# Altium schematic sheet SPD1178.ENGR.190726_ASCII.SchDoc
size A1; Revision: V01; SheetNumber: 1; SheetTotal: 1
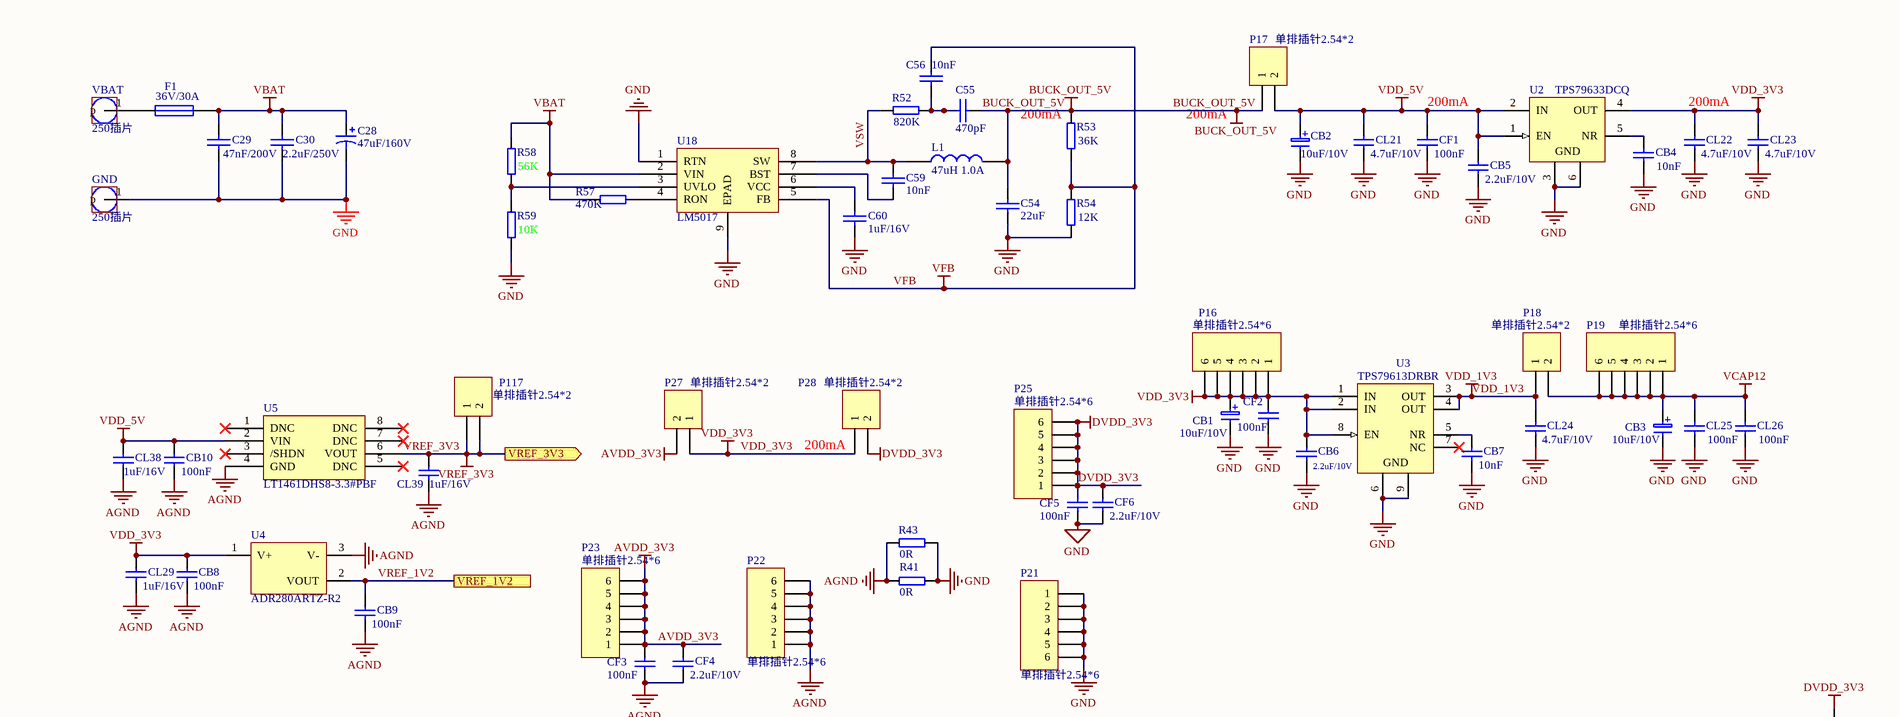
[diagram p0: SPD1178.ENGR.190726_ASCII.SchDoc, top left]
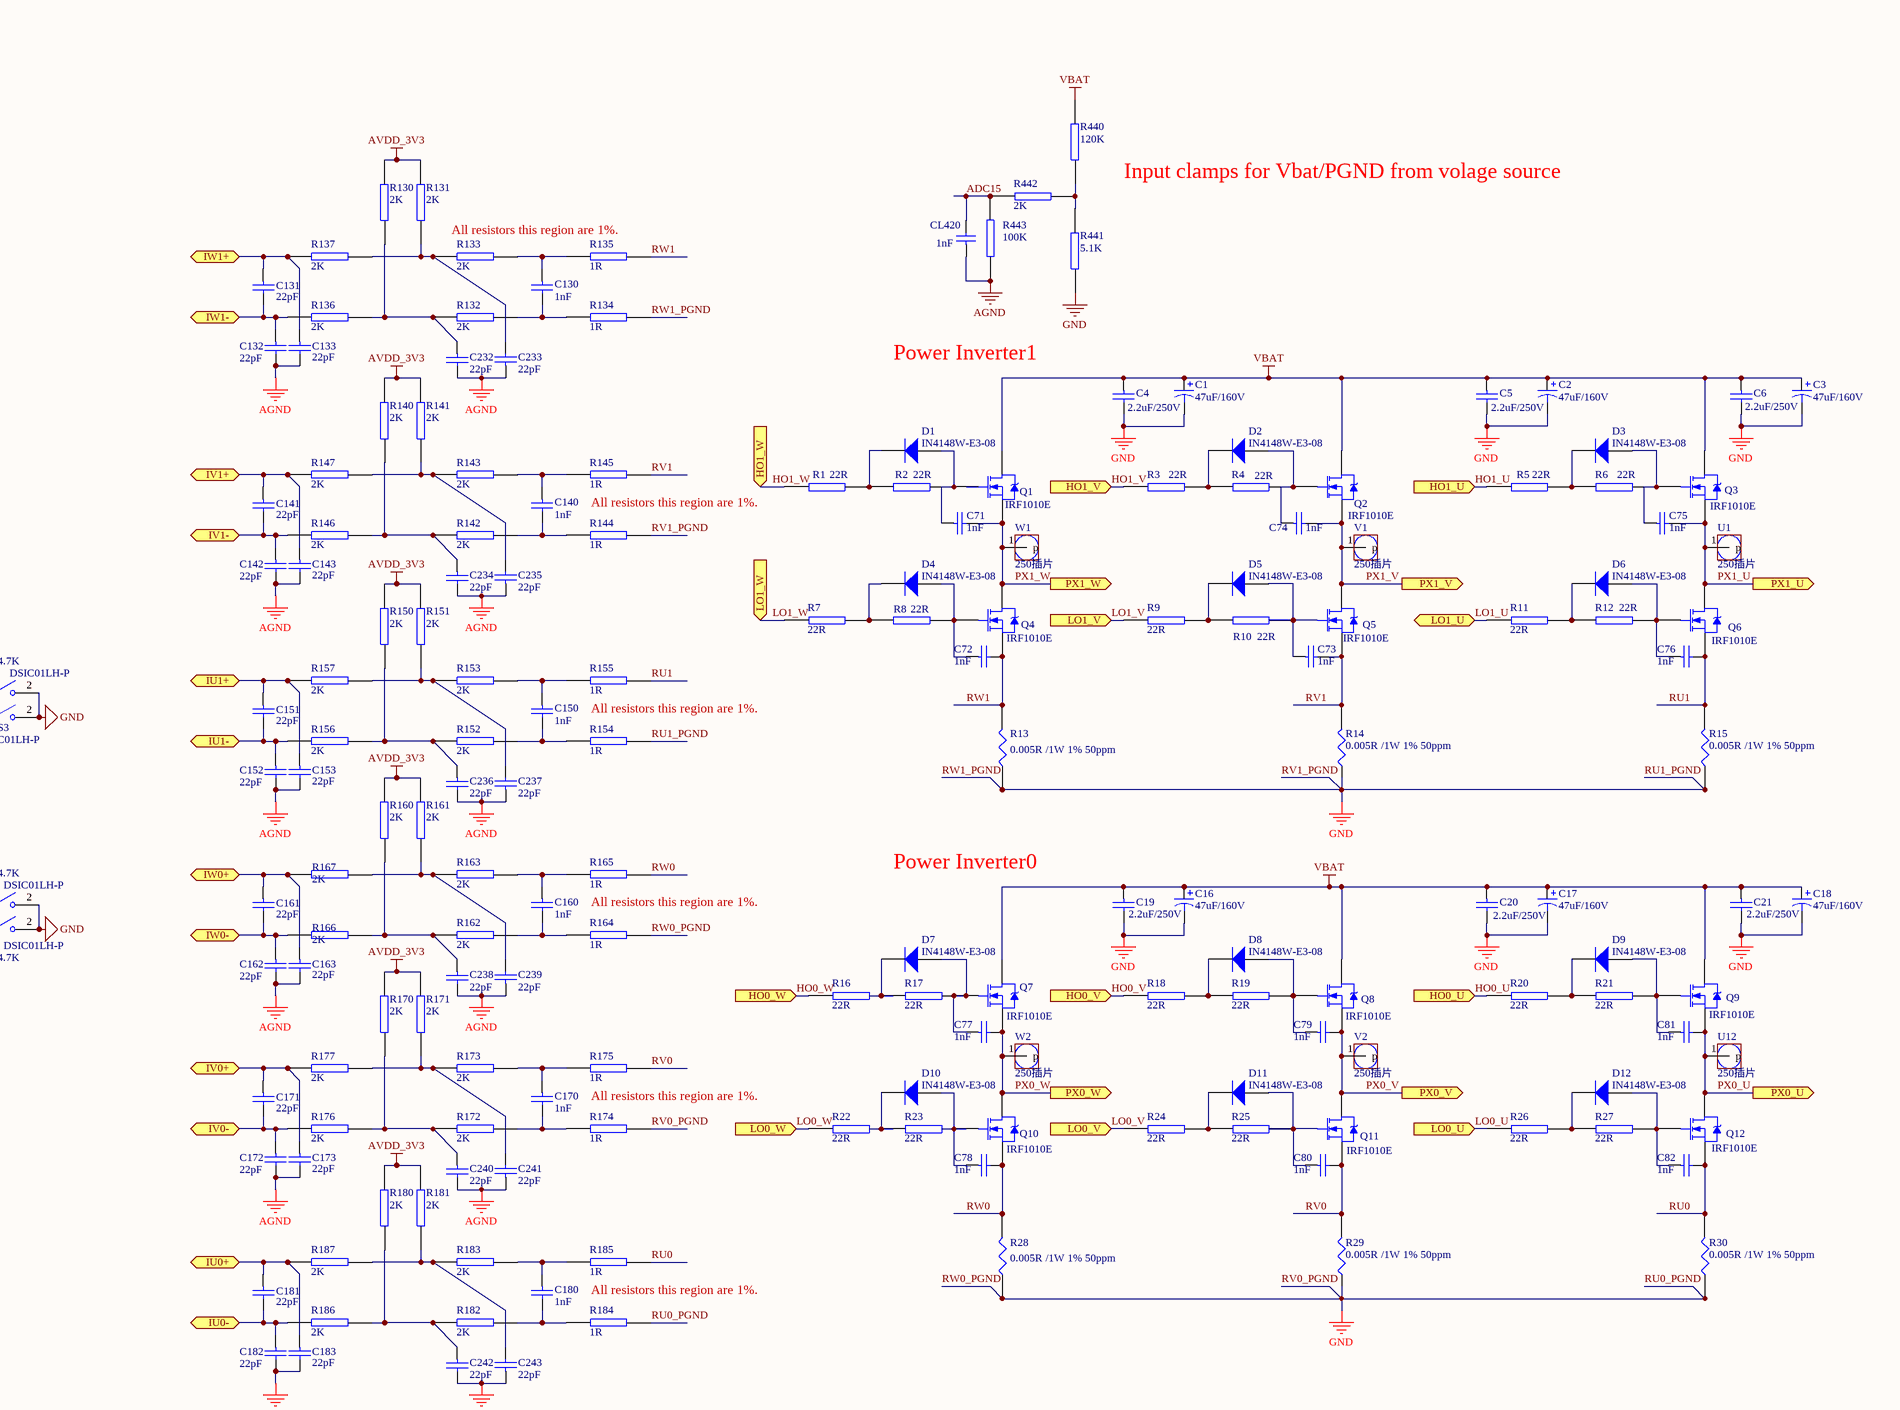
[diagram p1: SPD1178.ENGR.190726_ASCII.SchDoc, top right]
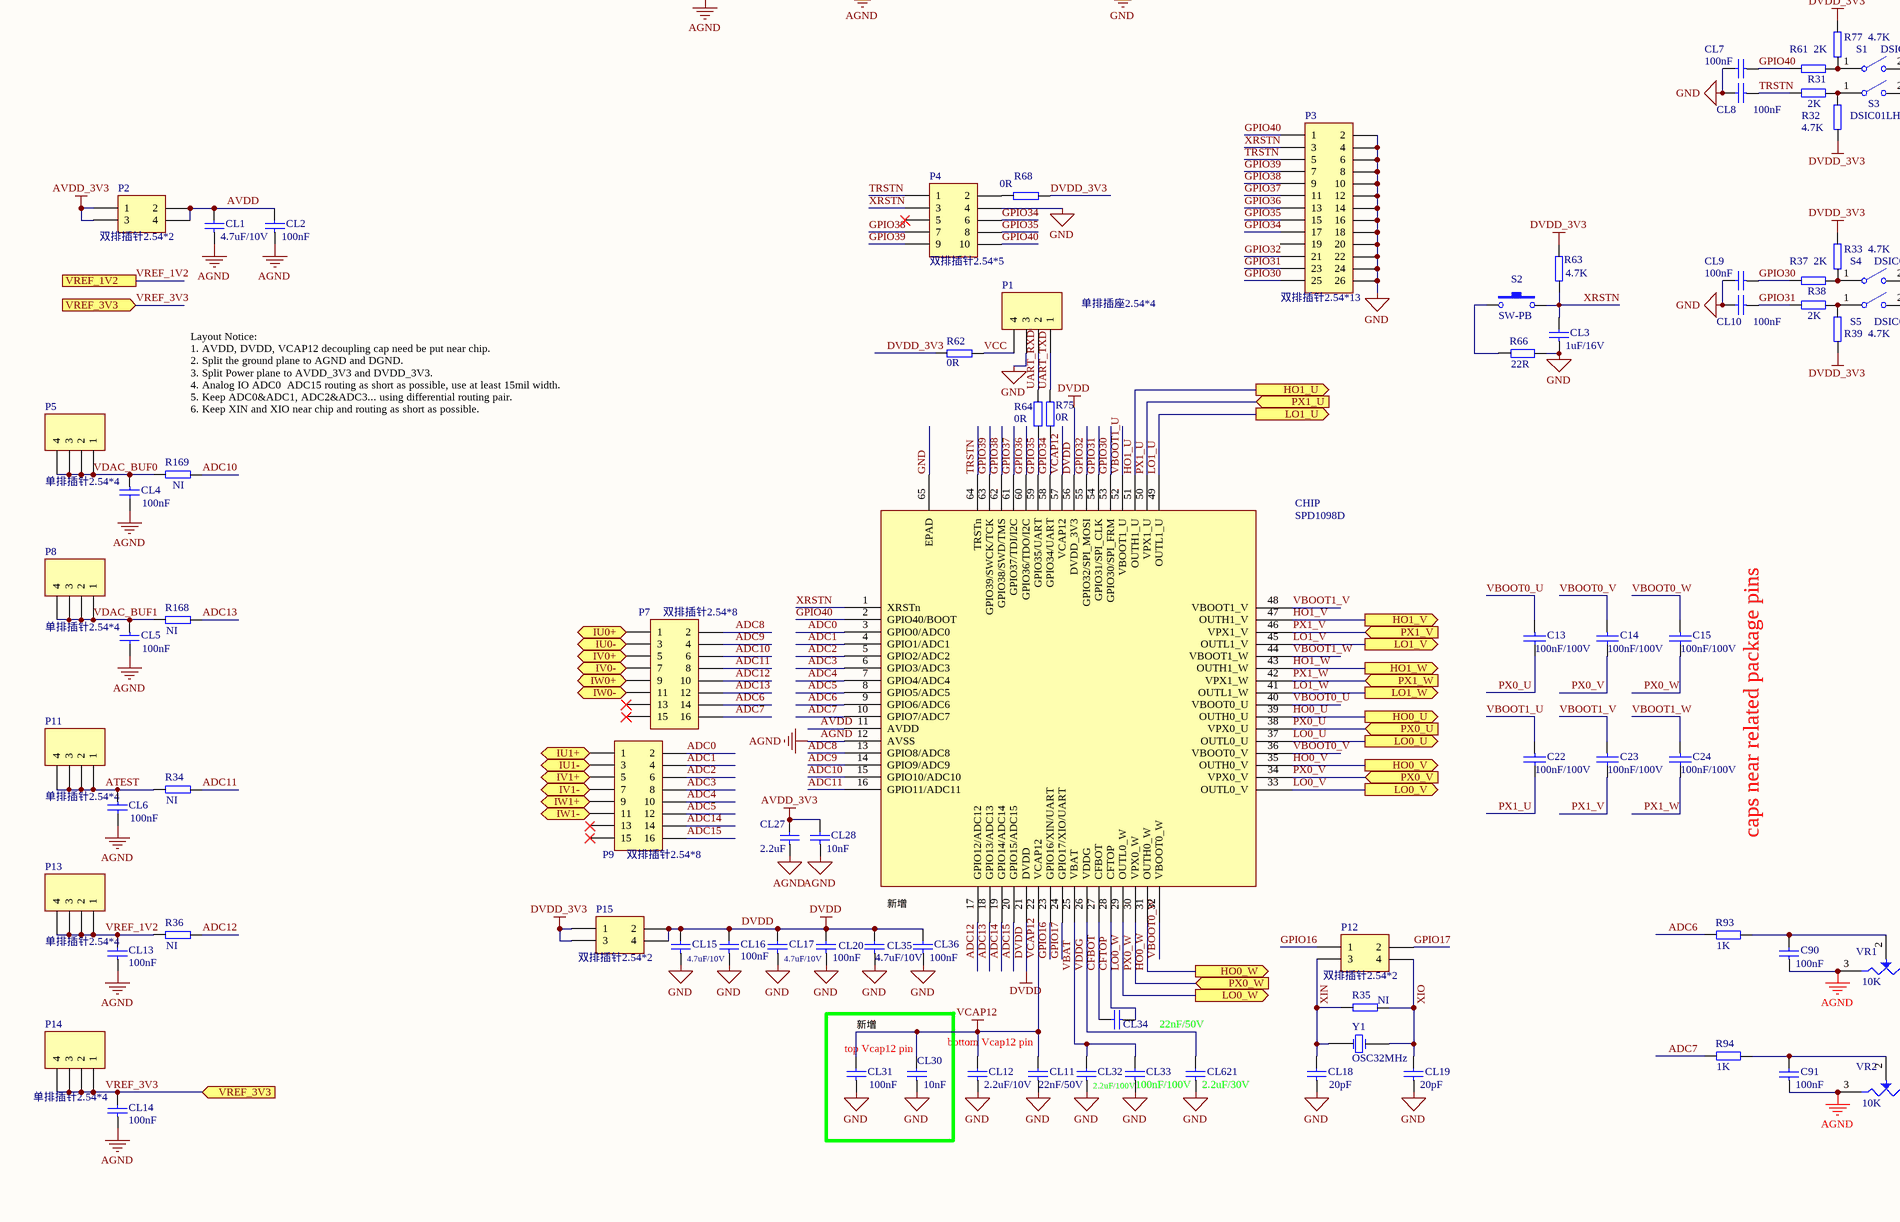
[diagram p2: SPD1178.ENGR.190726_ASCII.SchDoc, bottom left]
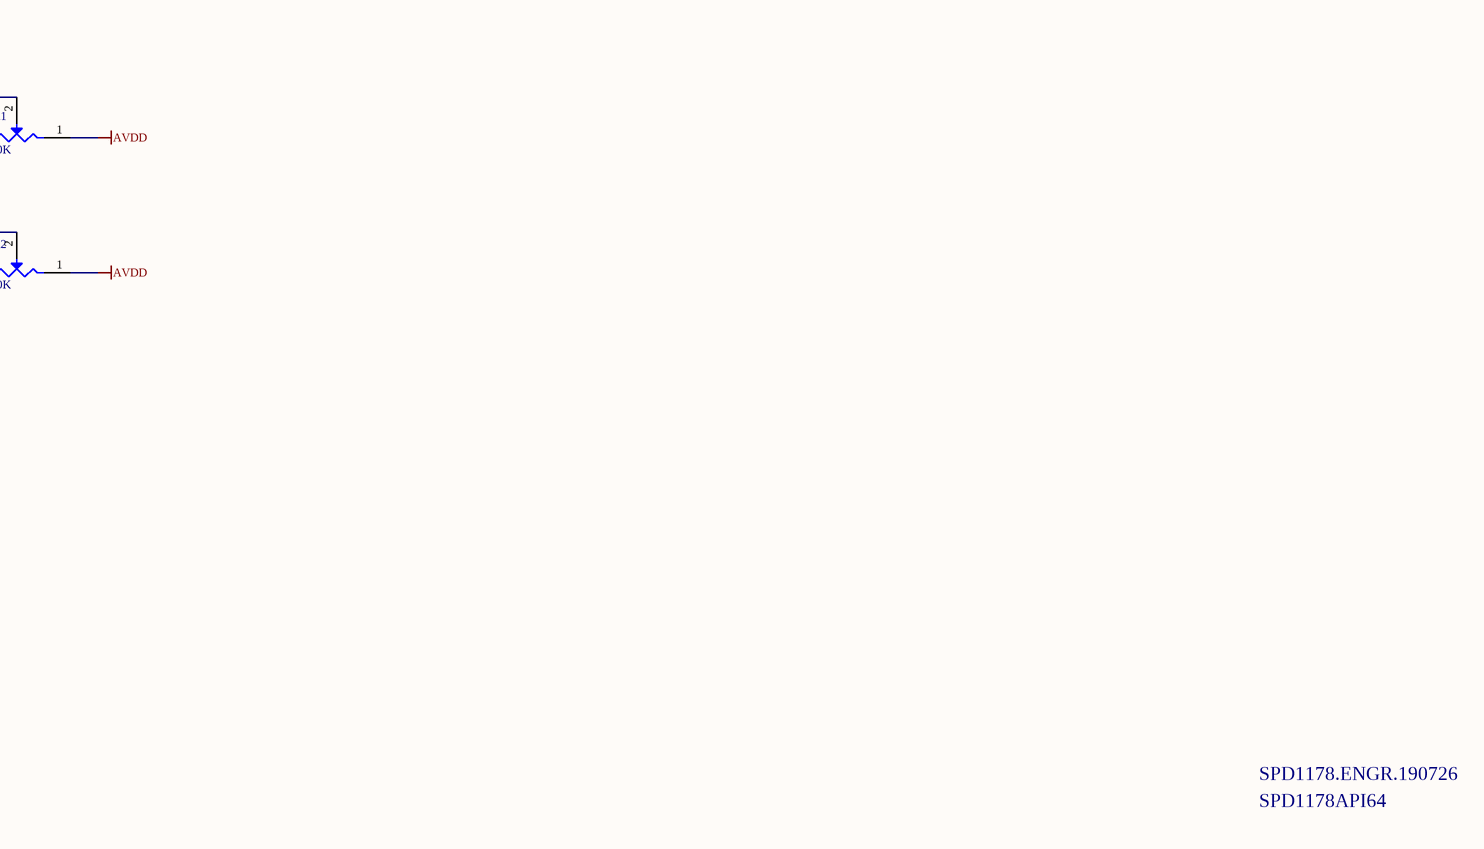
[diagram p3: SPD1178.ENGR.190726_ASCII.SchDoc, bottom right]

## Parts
C1  47uF/160V  [RB5.0/10]
C2  47uF/160V  [RB5.0/10]
C3  47uF/160V  [RB5.0/10]
C4  2.2uF/250V  [2220]
C5  2.2uF/250V  [2220]
C6  2.2uF/250V  [2220]
C13  100nF/100V  [C0603[1608]]
C14  100nF/100V  [C0603[1608]]
C15  100nF/100V  [C0603[1608]]
C16  47uF/160V  [RB5.0/10]
C17  47uF/160V  [RB5.0/10]
C18  47uF/160V  [RB5.0/10]
C19  2.2uF/250V  [2220]
C20  2.2uF/250V  [2220]
C21  2.2uF/250V  [2220]
C22  100nF/100V  [C0603[1608]]
C23  100nF/100V  [C0603[1608]]
C24  100nF/100V  [C0603[1608]]
C28  47uF/160V  [RB5.0/10]
C29  47nF/200V  [1206]
C30  2.2uF/250V  [2220]
C54  22uF  [0805]
C55  470pF  [C0603[1608]]
C56  10nF  [C0603[1608]]
C59  10nF  [C0603[1608]]
C60  1uF/16V  [C0603[1608]]
C71  1nF  [C0603[1608]]
C72  1nF  [C0603[1608]]
C73  1nF  [C0603[1608]]
C74  1nF  [C0603[1608]]
C75  1nF  [C0603[1608]]
C76  1nF  [C0603[1608]]
C77  1nF  [C0603[1608]]
C78  1nF  [C0603[1608]]
C79  1nF  [C0603[1608]]
C80  1nF  [C0603[1608]]
C81  1nF  [C0603[1608]]
C82  1nF  [C0603[1608]]
C90  100nF  [C0603[1608]]
C91  100nF  [C0603[1608]]
C130  1nF  [C0603[1608]]
C131  22pF  [C0603[1608]]
C132  22pF  [C0603[1608]]
C133  22pF  [C0603[1608]]
C140  1nF  [C0603[1608]]
C141  22pF  [C0603[1608]]
C142  22pF  [C0603[1608]]
C143  22pF  [C0603[1608]]
C150  1nF  [C0603[1608]]
C151  22pF  [C0603[1608]]
C152  22pF  [C0603[1608]]
C153  22pF  [C0603[1608]]
C160  1nF  [C0603[1608]]
C161  22pF  [C0603[1608]]
C162  22pF  [C0603[1608]]
C163  22pF  [C0603[1608]]
C170  1nF  [C0603[1608]]
C171  22pF  [C0603[1608]]
C172  22pF  [C0603[1608]]
C173  22pF  [C0603[1608]]
C180  1nF  [C0603[1608]]
C181  22pF  [C0603[1608]]
C182  22pF  [C0603[1608]]
C183  22pF  [C0603[1608]]
C232  22pF  [C0603[1608]]
C233  22pF  [C0603[1608]]
C234  22pF  [C0603[1608]]
C235  22pF  [C0603[1608]]
C236  22pF  [C0603[1608]]
C237  22pF  [C0603[1608]]
C238  22pF  [C0603[1608]]
C239  22pF  [C0603[1608]]
C240  22pF  [C0603[1608]]
C241  22pF  [C0603[1608]]
C242  22pF  [C0603[1608]]
C243  22pF  [C0603[1608]]
CB1  10uF/10V  [TC3216-A]
CB2  10uF/10V  [TC3216-A]
CB3  10uF/10V  [TC3216-A]
CB4  10nF  [C0603[1608]]
CB5  2.2uF/10V  [C0603[1608]]
CB6  2.2uF/10V  [C0603[1608]]
CB7  10nF  [C0603[1608]]
CB8  100nF  [C0603[1608]]
CB9  100nF  [C0603[1608]]
CB10  100nF  [C0603[1608]]
CF1  100nF  [C0603[1608]]
CF2  100nF  [C0603[1608]]
CF3  100nF  [C0603[1608]]
CF4  2.2uF/10V  [C0603[1608]]
CF5  100nF  [C0603[1608]]
CF6  2.2uF/10V  [C0603[1608]]
CHIP  SPD1098D  [QFN64L_201707]
CL1  4.7uF/10V  [C0603[1608]]
CL2  100nF  [C0603[1608]]
CL3  1uF/16V  [C0603[1608]]
CL4  100nF  [C0603[1608]]
CL5  100nF  [C0603[1608]]
CL6  100nF  [C0603[1608]]
CL7  100nF  [C0603[1608]]
CL8  100nF  [C0603[1608]]
CL9  100nF  [C0603[1608]]
CL10  100nF  [C0603[1608]]
CL11  22nF/50V  [C0603[1608]]
CL12  2.2uF/10V  [C0603[1608]]
CL13  100nF  [C0603[1608]]
CL14  100nF  [C0603[1608]]
CL15  4.7uF/10V  [C0603[1608]]
CL16  100nF  [C0603[1608]]
CL17  4.7uF/10V  [C0603[1608]]
CL18  20pF  [C0603[1608]]
CL19  20pF  [C0603[1608]]
CL20  100nF  [C0603[1608]]
CL21  4.7uF/10V  [C0603[1608]]
CL22  4.7uF/10V  [C0603[1608]]
CL23  4.7uF/10V  [C0603[1608]]
CL24  4.7uF/10V  [C0603[1608]]
CL25  100nF  [C0603[1608]]
CL26  100nF  [C0603[1608]]
CL27  2.2uF  [C0603[1608]]
CL28  10nF  [C0603[1608]]
CL29  1uF/16V  [C0603[1608]]
CL30  10nF  [C0603[1608]]
CL31  100nF  [C0603[1608]]
CL32  2.2uF/100V  [1206]
CL33  100nF/100V  [C0603[1608]]
CL34  22nF/50V  [C0603[1608]]
CL35  4.7uF/10V  [C0603[1608]]
CL36  100nF  [C0603[1608]]
CL38  1uF/16V  [C0603[1608]]
CL39  1uF/16V  [C0603[1608]]
CL420  1nF  [C0603[1608]]
CL621  2.2uF/30V  [0805]
D1  IN4148W-E3-08  [LL-34]
D2  IN4148W-E3-08  [LL-34]
D3  IN4148W-E3-08  [LL-34]
D4  IN4148W-E3-08  [LL-34]
D5  IN4148W-E3-08  [LL-34]
D6  IN4148W-E3-08  [LL-34]
D7  IN4148W-E3-08  [LL-34]
D8  IN4148W-E3-08  [LL-34]
D9  IN4148W-E3-08  [LL-34]
D10  IN4148W-E3-08  [LL-34]
D11  IN4148W-E3-08  [LL-34]
D12  IN4148W-E3-08  [LL-34]
F1  36V/30A  [F3]
GND  250插片  [PIN_L]
L1  47uH 1.0A  [1210R]
P1  单排插座2.54*4  [HDR1X4]
P2  双排插针2.54*2  [HDR2X2]
P3  双排插针2.54*13  [HDR2X13]
P4  双排插针2.54*5  [HDR2X5]
P5  单排插针2.54*4  [HDR1X4]
P7  双排插针2.54*8  [HDR2X8]
P8  单排插针2.54*4  [HDR1X4]
P9  双排插针2.54*8  [HDR2X8]
P11  单排插针2.54*4  [HDR1X4]
P12  双排插针2.54*2  [HDR2X2]
P13  单排插针2.54*4  [HDR1X4]
P14  单排插针2.54*4  [HDR1X4]
P15  双排插针2.54*2  [HDR2X2]
P16  单排插针2.54*6  [HDR1X6]
P17  单排插针2.54*2  [HDR1X2]
P18  单排插针2.54*2  [HDR1X2]
P19  单排插针2.54*6  [HDR1X6]
P21  单排插针2.54*6  [HDR1X6]
P22  单排插针2.54*6  [HDR1X6]
P23  单排插针2.54*6  [HDR1X6]
P25  单排插针2.54*6  [HDR1X6]
P27  单排插针2.54*2  [HDR1X2]
P28  单排插针2.54*2  [HDR1X2]
P117  单排插针2.54*2  [HDR1X2]
Q1  IRF1010E  [TO-220AB]
Q2  IRF1010E  [TO-220AB]
Q3  IRF1010E  [TO-220AB]
Q4  IRF1010E  [TO-220AB]
Q5  IRF1010E  [TO-220AB]
Q6  IRF1010E  [TO-220AB]
Q7  IRF1010E  [TO-220AB]
Q8  IRF1010E  [TO-220AB]
Q9  IRF1010E  [TO-220AB]
Q10  IRF1010E  [TO-220AB]
Q11  IRF1010E  [TO-220AB]
Q12  IRF1010E  [TO-220AB]
R1  22R  [R0603[1608]]
R2  22R  [R0603[1608]]
R3  22R  [R0603[1608]]
R4  22R  [R0603[1608]]
R5  22R  [R0603[1608]]
R6  22R  [R0603[1608]]
R7  22R  [R0603[1608]]
R8  22R  [R0603[1608]]
R9  22R  [R0603[1608]]
R10  22R  [R0603[1608]]
R11  22R  [R0603[1608]]
R12  22R  [R0603[1608]]
R13  0.005R /1W 1% 50ppm  [2512]
R14  0.005R /1W 1% 50ppm  [2512]
R15  0.005R /1W 1% 50ppm  [2512]
R16  22R  [R0603[1608]]
R17  22R  [R0603[1608]]
R18  22R  [R0603[1608]]
R19  22R  [R0603[1608]]
R20  22R  [R0603[1608]]
R21  22R  [R0603[1608]]
R22  22R  [R0603[1608]]
R23  22R  [R0603[1608]]
R24  22R  [R0603[1608]]
R25  22R  [R0603[1608]]
R26  22R  [R0603[1608]]
R27  22R  [R0603[1608]]
R28  0.005R /1W 1% 50ppm  [2512]
R29  0.005R /1W 1% 50ppm  [2512]
R30  0.005R /1W 1% 50ppm  [2512]
R31  2K  [R0603[1608]]
R32  4.7K  [R0603[1608]]
R33  4.7K  [R0603[1608]]
R34  NI  [R0603[1608]]
R35  NI  [R0603[1608]]
R36  NI  [R0603[1608]]
R37  2K  [R0603[1608]]
R38  2K  [R0603[1608]]
R39  4.7K  [R0603[1608]]
R41  0R  [R0603[1608]]
R43  0R  [R0603[1608]]
R52  820K  [R0603[1608]]
R53  36K  [R0805[2012]]
R54  12K  [R0805[2012]]
R57  470K  [R0603[1608]]
R58  56K  [R0805[2012]]
R59  10K  [R0805[2012]]
R61  2K  [R0603[1608]]
R62  0R  [R0603[1608]]
R63  4.7K  [R0603[1608]]
R64  0R  [R0603[1608]]
R66  22R  [R0603[1608]]
R68  0R  [R0603[1608]]
R75  0R  [R0603[1608]]
R77  4.7K  [R0603[1608]]
R93  1K  [R0603[1608]]
R94  1K  [R0603[1608]]
R130  2K  [R0603[1608]]
R131  2K  [R0603[1608]]
R132  2K  [R0603[1608]]
R133  2K  [R0603[1608]]
R134  1R  [R0603[1608]]
R135  1R  [R0603[1608]]
R136  2K  [R0603[1608]]
R137  2K  [R0603[1608]]
R140  2K  [R0603[1608]]
R141  2K  [R0603[1608]]
R142  2K  [R0603[1608]]
R143  2K  [R0603[1608]]
R144  1R  [R0603[1608]]
R145  1R  [R0603[1608]]
R146  2K  [R0603[1608]]
R147  2K  [R0603[1608]]
R150  2K  [R0603[1608]]
R151  2K  [R0603[1608]]
R152  2K  [R0603[1608]]
R153  2K  [R0603[1608]]
R154  1R  [R0603[1608]]
R155  1R  [R0603[1608]]
R156  2K  [R0603[1608]]
R157  2K  [R0603[1608]]
R160  2K  [R0603[1608]]
R161  2K  [R0603[1608]]
R162  2K  [R0603[1608]]
R163  2K  [R0603[1608]]
R164  1R  [R0603[1608]]
R165  1R  [R0603[1608]]
R166  2K  [R0603[1608]]
R167  2K  [R0603[1608]]
R168  NI  [R0603[1608]]
R169  NI  [R0603[1608]]
R170  2K  [R0603[1608]]
R171  2K  [R0603[1608]]
R172  2K  [R0603[1608]]
R173  2K  [R0603[1608]]
R174  1R  [R0603[1608]]
R175  1R  [R0603[1608]]
R176  2K  [R0603[1608]]
R177  2K  [R0603[1608]]
R180  2K  [R0603[1608]]
R181  2K  [R0603[1608]]
R182  2K  [R0603[1608]]
R183  2K  [R0603[1608]]
R184  1R  [R0603[1608]]
R185  1R  [R0603[1608]]
R186  2K  [R0603[1608]]
R187  2K  [R0603[1608]]
R440  120K  [0805]
R441  5.1K  [0805]
R442  2K  [R0603[1608]]
R443  100K  [R0603[1608]]
S1  DSIC01LH-P  [S7.62*1]
S2  SW-PB  [SWITCH-4]
S3  DSIC01LH-P  [S7.62*1]
S4  DSIC01LH-P  [S7.62*1]
S5  DSIC01LH-P  [S7.62*1]
U1  250插片  [PIN_L]
U2  TPS79633DCQ  [TI-DCQ6_N]
U3  TPS79613DRBR  [TI-DRB8-2400X1650TP_V]
U4  ADR280ARTZ-R2  [ADI-RT-3_N]
U5  LT1461DHS8-3.3#PBF  [S8 PACKAGE]
U12  250插片  [PIN_L]
U18  LM5017  [DDA]
V1  250插片  [PIN_L]
V2  250插片  [PIN_L]
VBAT  250插片  [PIN_L]
VR1  10K  [VR_3386_Knob]
VR2  10K  [VR_3386_Knob]
W1  250插片  [PIN_L]
W2  250插片  [PIN_L]
Y1  OSC32MHz  [OSC]

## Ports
HO0_U (in), HO0_U (out), HO0_V (in), HO0_V (out), HO0_W (in), HO0_W (out), HO1_U (in), HO1_U (out), HO1_V (in), HO1_V (out), HO1_W (in), HO1_W (out), IU0+ (bidir), IU0- (bidir), IU1+ (bidir), IU1- (bidir), IV0+ (bidir), IV0- (bidir), IV1+ (bidir), IV1- (bidir), IW0+ (bidir), IW0- (bidir), IW1+ (bidir), IW1- (bidir), LO0_U (in), LO0_U (out), LO0_V (in), LO0_V (out), LO0_W (in), LO0_W (out), LO1_U (bidir), LO1_U (out), LO1_V (in), LO1_V (out), LO1_W (in), LO1_W (out), PX0_U (in), PX0_U (out), PX0_V (in), PX0_V (out), PX0_W (in), PX0_W (out), PX1_U (in), PX1_U (out), PX1_V (in), PX1_V (out), PX1_W (in), PX1_W (out), VREF_1V2, VREF_3V3 (in), VREF_3V3 (out)

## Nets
AGND: C90.1 C91.1 C132.2 C133.2 C142.2 C143.2 C152.2 C153.2 C162.2 C163.2 C172.2 C173.2 C182.2 C183.2 C232.2 C233.1 C234.2 C235.1 C236.2 C237.1 C238.2 C239.1 C240.2 C241.1 C242.2 C243.1 CB8.1 CB9.1 CB10.1 CF3.2 CF4.2 CHIP.12(AVSS) CL1.1 CL2.1 CL4.2 CL5.2 CL6.2 CL13.1 CL14.1 CL27.1 CL28.1 CL29.1 CL38.1 CL39.1 CL420.1 P22.1 P22.2 P22.3 P22.4 P22.5 P22.6 R41.1 R43.1 R443.2 U4.3(V-) U5.4(GND) VR1.3(W) VR2.3(W)
AVDD: CHIP.11(AVDD) CL1.2 CL2.2 P2.2 P2.4 VR1.1 VR2.1
AVDD_3V3: CF3.1 CF4.1 CL27.2 CL28.2 P2.1 P2.3 P23.1 P23.2 P23.3 P23.4 P23.5 P23.6 P27.2 R130.2 R131.2 R140.2 R141.2 R150.2 R151.2 R160.2 R161.2 R170.2 R171.2 R180.2 R181.2
BUCK_OUT_5V: C54.1 C55.2 L1.2 P17.1 R53.1
DVDD: CHIP.21(DVDD) CHIP.56(DVDD_3V3) CL15.2 CL16.2 CL17.2 CL20.2 CL35.2 CL36.2 P15.2 P15.4
DVDD_3V3: CF5.1 CF6.1 P15.1 P15.3 P25.1 P25.2 P25.3 P25.4 P25.5 P25.6 P28.2 R32.1 R33.1 R39.1 R62.2 R63.2 R68.2 R77.1
GND: C1.2 C2.2 C3.2 C4.2 C5.2 C6.2 C16.2 C17.2 C18.2 C19.2 C20.2 C21.2 C28.2 C29.2 C30.2 C54.2 C60.1 CB1.2(K) CB2.2(K) CB3.2(K) CB4.2 CB5.2 CB6.2 CB7.2 CF1.2 CF2.2 CF5.2 CF6.2 CHIP.65(EPAD) CL3.1 CL7.2 CL8.2 CL9.2 CL10.2 CL11.1 CL12.1 CL15.1 CL16.1 CL17.1 CL18.1 CL19.1 CL20.1 CL21.2 CL22.2 CL23.2 CL24.2 CL25.2 CL26.2 CL30.1 CL31.1 CL32.1 CL33.1 CL35.1 CL36.1 CL621.1 GND.1(p) P1.3 P3.2 P3.4 P3.6 P3.8 P3.10 P3.12 P3.14 P3.16 P3.18 P3.20 P3.22 P3.24 P3.26 P4.4 P21.1 P21.2 P21.3 P21.4 P21.5 P21.6 R13.1 R14.1 R15.1 R28.1 R29.1 R30.1 R41.2 R43.2 R54.2 R59.2 R66.1 R134.1 R144.1 R154.1 R164.1 R174.1 R184.1 R441.1 S1.2 S3.2 S4.2 S5.2 U2.3(GND) U2.6(GND) U3.6(GND) U3.9(GND) U18.1(RTN) U18.9(EPAD)  [also labelled RU0_PGND, RU1_PGND, RV0_PGND, RV1_PGND, RW0_PGND, RW1_PGND]
VBAT: C1.1 C2.1 C3.1 C4.1 C5.1 C6.1 C16.1 C17.1 C18.1 C19.1 C20.1 C21.1 C28.1 C29.1 C30.1 CHIP.25(VBAT) CL32.2 CL33.2 F1.2 Q1.2(D) Q2.2(D) Q3.2(D) Q7.2(D) Q8.2(D) Q9.2(D) R57.1 R58.1 R440.2 U18.2(VIN)
VCAP12: CB3.1(A) CHIP.22(VCAP12) CHIP.57(VCAP12) CL11.2 CL12.2 CL25.1 CL26.1 CL30.2 CL31.2 P18.2 P19.1 P19.2 P19.3 P19.4 P19.5 P19.6
VDD_1V3: CL24.1 P18.1 U3.3(OUT) U3.4(OUT)
VDD_3V3: CB1.1(A) CB6.1 CB8.2 CF2.1 CL22.1 CL23.1 CL29.2 P16.1 P16.2 P16.3 P16.4 P16.5 P16.6 P27.1 P28.1 U2.4(OUT) U3.1(IN) U3.2(IN) U3.8(EN) U4.1(V+)
VDD_5V: CB2.1(A) CB5.1 CB10.2 CF1.1 CL21.1 CL38.2 P17.2 U2.1(EN) U2.2(IN) U5.2(VIN)
VFB: C56.2 R53.2 R54.1 U18.5(FB)
VREF_3V3: CL14.2 CL39.2 P14.1 P14.2 P14.3 P14.4 P117.1 P117.2 U5.6(VOUT) ; port VREF_3V3
ADC0: CHIP.3(GPIO0/ADC0) P9.2
ADC1: CHIP.4(GPIO1/ADC1) P9.4
ADC2: CHIP.5(GPIO2/ADC2) P9.6
ADC3: CHIP.6(GPIO3/ADC3) P9.8
ADC4: CHIP.7(GPIO4/ADC4) P9.10
ADC5: CHIP.8(GPIO5/ADC5) P9.12
ADC6: CHIP.9(GPIO6/ADC6) P7.14 R93.2
ADC7: CHIP.10(GPIO7/ADC7) P7.16 R94.2
ADC8: CHIP.13(GPIO8/ADC8) P7.2
ADC9: CHIP.14(GPIO9/ADC9) P7.4
ADC10: CHIP.15(GPIO10/ADC10) P7.6 R169.2
ADC11: CHIP.16(GPIO11/ADC11) P7.8 R34.2
ADC12: CHIP.17(GPIO12/ADC12) P7.10 R36.2
ADC13: CHIP.18(GPIO13/ADC13) P7.12 R168.2
ADC14: CHIP.19(GPIO14/ADC14) P9.14
ADC15: CHIP.20(GPIO15/ADC15) CL420.2 P9.16 R442.1 R443.1
ATEST: CL6.1 P11.1 P11.2 P11.3 P11.4 R34.1
CFBOT: CHIP.27(CFBOT) CL34.2
CFTOP: CHIP.28(CFTOP) CL34.1
GPIO16: CHIP.23(GPIO16/XIN/UART) P12.1
GPIO17: CHIP.24(GPIO17/XIO/UART) P12.2
GPIO30: CHIP.53(GPIO30/SPI_FRM) CL9.1 P3.25 R37.1
GPIO31: CHIP.54(GPIO31/SPI_CLK) CL10.1 P3.23 R38.1
GPIO32: CHIP.55(GPIO32/SPI_MOSI) P3.21
GPIO34: CHIP.58(GPIO34/UART) P3.17 P4.6 R75.1
GPIO35: CHIP.59(GPIO35/UART) P3.15 P4.8 R64.1
GPIO36: CHIP.60(GPIO36/TDO/I2C) P3.13
GPIO37: CHIP.61(GPIO37/TDI/I2C) P3.11
GPIO38: CHIP.62(GPIO38/SWD/TMS) P3.9 P4.7
GPIO39: CHIP.63(GPIO39/SWCK/TCK) P3.7 P4.9
GPIO40: CHIP.2(GPIO40/BOOT) CL7.1 P3.1 P4.10 R61.1
HO0_U: CHIP.39(OUTH0_U) R20.1 ; port HO0_U
HO0_V: CHIP.35(OUTH0_V) R18.1 ; port HO0_V
HO0_W: CHIP.31(OUTH0_W) R16.1 ; port HO0_W
HO1_U: CHIP.51(OUTH1_U) R5.1 ; port HO1_U
HO1_V: CHIP.47(OUTH1_V) R3.1 ; port HO1_V
HO1_W: CHIP.43(OUTH1_W) R1.1 ; port HO1_W
IU0+: C181.1 C183.1 P7.1 R187.2 ; port IU0+
IU0-: C181.2 C182.1 P7.3 R186.2 ; port IU0-
IU1+: C151.1 C153.1 P9.1 R157.2 ; port IU1+
IU1-: C151.2 C152.1 P9.3 R156.2 ; port IU1-
IV0+: C171.1 C173.1 P7.5 R177.2 ; port IV0+
IV0-: C171.2 C172.1 P7.7 R176.2 ; port IV0-
IV1+: C141.1 C143.1 P9.5 R147.2 ; port IV1+
IV1-: C141.2 C142.1 P9.7 R146.2 ; port IV1-
IW0+: C161.1 C163.1 P7.9 R167.2 ; port IW0+
IW0-: C161.2 C162.1 P7.11 R166.2 ; port IW0-
IW1+: C131.1 C133.1 P9.9 R137.2 ; port IW1+
IW1-: C131.2 C132.1 P9.11 R136.2 ; port IW1-
LO0_U: CHIP.37(OUTL0_U) R26.1 ; port LO0_U
LO0_V: CHIP.33(OUTL0_V) R24.1 ; port LO0_V
LO0_W: CHIP.29(OUTL0_W) R22.1 ; port LO0_W
LO1_U: CHIP.49(OUTL1_U) R11.1 ; port LO1_U
LO1_V: CHIP.45(OUTL1_V) R9.1 ; port LO1_V
LO1_W: CHIP.41(OUTL1_W) R7.1 ; port LO1_W
PX0_U: C13.2 C81.2 CHIP.38(VPX0_U) Q9.3(S) Q12.2(D) U12.1(p) ; port PX0_U
PX0_V: C14.2 C79.2 CHIP.34(VPX0_V) Q8.3(S) Q11.2(D) V2.1(p) ; port PX0_V
PX0_W: C15.2 C77.2 CHIP.30(VPX0_W) Q7.3(S) Q10.2(D) W2.1(p) ; port PX0_W
PX1_U: C22.2 C75.2 CHIP.50(VPX1_U) Q3.3(S) Q6.2(D) U1.1(p) ; port PX1_U
PX1_V: C23.2 C74.2 CHIP.46(VPX1_V) Q2.3(S) Q5.2(D) V1.1(p) ; port PX1_V
PX1_W: C24.2 C71.2 CHIP.42(VPX1_W) Q1.3(S) Q4.2(D) W1.1(p) ; port PX1_W
RU0: C82.2 Q12.3(S) R30.2 R185.1
RU1: C76.2 Q6.3(S) R15.2 R155.1
RV0: C80.2 Q11.3(S) R29.2 R175.1
RV1: C73.2 Q5.3(S) R14.2 R145.1
RW0: C78.2 Q10.3(S) R28.2 R165.1
RW1: C72.2 Q4.3(S) R13.2 R135.1
TRSTN: CHIP.64(TRSTn) CL8.1 P3.5 P4.1 R31.1
UART_RXD: P1.2 R64.2
UART_TXD: P1.1 R75.2
VBOOT0_U: C13.1 CHIP.40(VBOOT0_U)
VBOOT0_V: C14.1 CHIP.36(VBOOT0_V)
VBOOT0_W: C15.1 CHIP.32(VBOOT0_W)
VBOOT1_U: C22.1 CHIP.52(VBOOT1_U)
VBOOT1_V: C23.1 CHIP.48(VBOOT1_V)
VBOOT1_W: C24.1 CHIP.44(VBOOT1_W)
VCC: P1.4 R62.1
VDAC_BUF0: CL4.1 P5.1 P5.2 P5.3 P5.4 R169.1
VDAC_BUF1: CL5.1 P8.1 P8.2 P8.3 P8.4 R168.1
VDDG: CHIP.26(VDDG) CL621.2
VREF_1V2: CB9.2 CL13.2 P13.1 P13.2 P13.3 P13.4 R36.1 U4.2(VOUT) ; port VREF_1V2
VSW: C59.2 L1.1 R52.2 U18.8(SW)
XIN: CL18.2 P12.3 R35.1 Y1.1(OSC1)
XIO: CL19.2 P12.4 R35.2 Y1.2(OSC2)
XRSTN: CHIP.1(XRSTn) CL3.2 P3.3 P4.3 R63.1 S2.2
NetC55_1: C55.1 C56.1 R52.1
NetC59_1: C59.1 U18.7(BST)
NetC60_2: C60.2 U18.6(VCC)
NetC71_1: C71.1 D1.1(A) Q1.1(G) R2.2
NetC72_1: C72.1 D4.1(A) Q4.1(G) R8.2
NetC73_1: C73.1 D5.1(A) Q5.1(G) R10.2
NetC74_1: C74.1 D2.1(A) Q2.1(G) R4.2
NetC75_1: C75.1 D3.1(A) Q3.1(G) R6.2
NetC76_1: C76.1 D6.1(A) Q6.1(G) R12.2
NetC77_1: C77.1 D7.1(A) Q7.1(G) R17.2
NetC78_1: C78.1 D10.1(A) Q10.1(G) R23.2
NetC79_1: C79.1 D8.1(A) Q8.1(G) R19.2
NetC80_1: C80.1 D11.1(A) Q11.1(G) R25.2
NetC81_1: C81.1 D9.1(A) Q9.1(G) R21.2
NetC82_1: C82.1 D12.1(A) Q12.1(G) R27.2
NetC90_2: C90.2 R93.1 VR1.2
NetC91_2: C91.2 R94.1 VR2.2
NetC130_1: C130.1 R133.1 R135.2
NetC130_2: C130.2 R132.1 R134.2
NetC140_1: C140.1 R143.1 R145.2
NetC140_2: C140.2 R142.1 R144.2
NetC150_1: C150.1 R153.1 R155.2
NetC150_2: C150.2 R152.1 R154.2
NetC160_1: C160.1 R163.1 R165.2
NetC160_2: C160.2 R162.1 R164.2
NetC170_1: C170.1 R173.1 R175.2
NetC170_2: C170.2 R172.1 R174.2
NetC180_1: C180.1 R183.1 R185.2
NetC180_2: C180.2 R182.1 R184.2
NetC232_1: C232.1 R130.1 R132.2 R136.1
NetC233_2: C233.2 R131.1 R133.2 R137.1
NetC234_1: C234.1 R140.1 R142.2 R146.1
NetC235_2: C235.2 R141.1 R143.2 R147.1
NetC236_1: C236.1 R150.1 R152.2 R156.1
NetC237_2: C237.2 R151.1 R153.2 R157.1
NetC238_1: C238.1 R160.1 R162.2 R166.1
NetC239_2: C239.2 R161.1 R163.2 R167.1
NetC240_1: C240.1 R170.1 R172.2 R176.1
NetC241_2: C241.2 R171.1 R173.2 R177.1
NetC242_1: C242.1 R180.1 R182.2 R186.1
NetC243_2: C243.2 R181.1 R183.2 R187.1
NetCB4_1: CB4.1 U2.5(NR)
NetCB7_1: CB7.1 U3.5(NR)
NetD1_2: D1.2(K) R1.2 R2.1
NetD2_2: D2.2(K) R3.2 R4.1
NetD3_2: D3.2(K) R5.2 R6.1
NetD4_2: D4.2(K) R7.2 R8.1
NetD5_2: D5.2(K) R9.2 R10.1
NetD6_2: D6.2(K) R11.2 R12.1
NetD7_2: D7.2(K) R16.2 R17.1
NetD8_2: D8.2(K) R18.2 R19.1
NetD9_2: D9.2(K) R20.2 R21.1
NetD10_2: D10.2(K) R22.2 R23.1
NetD11_2: D11.2(K) R24.2 R25.1
NetD12_2: D12.2(K) R26.2 R27.1
NetF1_1: F1.1 VBAT.1(p)
NetP4_2: P4.2 R68.1
NetR31_2: R31.2 R32.2 S3.1
NetR33_2: R33.2 R37.2 S4.1
NetR38_2: R38.2 R39.2 S5.1
NetR57_2: R57.2 U18.4(RON)
NetR58_2: R58.2 R59.1 U18.3(UVLO)
NetR61_2: R61.2 R77.2 S1.1
NetR66_2: R66.2 S2.1
NetR440_1: R440.1 R441.2 R442.2

Not connected (* = marked no-connect by the designer): P3 19; P4 5*; P7 13* 15*; P9 13* 15*; U3 7(NC)*; U5 1(DNC)* 3(/SHDN)* 5(DNC)* 7(DNC)* 8(DNC)*

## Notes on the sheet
- (near R53) 200mA
- (near P17) 200mA
- (near CF1) 200mA
- (near CL22) 200mA
- All resistors this region are 1%.
- Input clamps for Vbat/PGND from volage source
- Power Inverter1
- (near P28) 200mA
- (near R1) All resistors this region are 1%.
- Power Inverter0
- (near R169) Layout Notice:
  1. AVDD, DVDD, VCAP12 decoupling cap need be put near chip.
  2. Split the ground plane to AGND and DGND.
  3. Split Power plane to AVDD_3V3 and DVDD_3V3.
  4. Analog IO ADC0  ADC15 routing as short as possible, use at least 15mil width.
  5. Keep ADC0&ADC1, ADC2&ADC3... using differential routing pair.
  6. Keep XIN and XIO near chip and routing as short as possible.
- caps near related package pins
- (near CHIP) 新增
- top Vcap12 pin
- (near CL31) 新增
- bottom Vcap12 pin
- SPD1178.ENGR.190726
- SPD1178API64

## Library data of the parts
C1-C3 C16-C18 C28 = Cap Pol1: Polarized Capacitor (Radial); Value: 47uF
C4-C6 C13-C15 C19-C24 C29 C30 C54-C56 C59 C60 C71-C82 C130-C133 C140-C143 C150-C153 C160-C163 C170-C173 C180-C183 C232-C243 = CAP: Capacitor
C90 C91 CB8-CB10 CF1-CF3 CF5 CL2 CL13 CL14 CL16 CL20 CL26 CL36 = Capacitor Unpolarized: CAP CER 0.1UF 16V X7R 0603
CB1-CB3 = Capacitor Polarized: CAP TANT 10UF 10V 10% 1206
CB4 CB7 CL11 CL28 CL30 CL32-CL34 CL621 = Capacitor Unpolarized: CAP CER 10000PF 10V X7R 0603
CB5 CB6 CF4 CF6 CL12 CL27 CL31 CL420 = Capacitor Unpolarized: CAP CER 2.2UF 10V X7R 0603
CHIP = JOULE: 32-bit MCU with Double Motor Pre-driver
CL1 CL15 CL17 CL21-CL24 CL35 = Capacitor Unpolarized: CAP CER 4.7UF 10V X7S 0603
CL3 CL29 CL38 CL39 = Capacitor Unpolarized: CAP CER 1UF 16V X7R 0603
CL4-CL10 CL25 = Capacitor Unpolarized: Unpolarized Capacitor
CL18 CL19 = Capacitor Unpolarized: CAP CER 20PF 10V X7R 0603
D1-D12 = Diode: Default Diode
F1 = Fuse
GND U1 U12 V1 V2 VBAT W1 W2 = TP
L1 = INDUCTOR
P1 P5 P8 P11 P13 P14 = Header 4: Header, 4-Pin
P2 P12 P15 = Header 2X2: Header, 2-Pin, Dual row
P3 = Header 13X2: Header, 13-Pin, Dual row
P4 = Header 5X2: Header, 5-Pin, Dual row
P7 P9 = Header 8X2: Header, 8-Pin, Dual row
P16 P19 P21-P23 P25 = Header 6: Header, 6-Pin
P17 P18 P27 P28 P117 = Header 2: Header, 2-Pin
Q1-Q12 = IRF1010E: HEXFET Power MOSFET; Note: Pin 2 is electrically connected to pin 4.; Sim Note: Thermal Model provided is not called on from main Subckt.
R1-R12 R16-R27 R130-R137 R140-R147 R150-R157 R160-R167 R170-R177 R180-R187 R440-R443 = RES2
R13-R15 R28-R30 = RES1
R31-R33 R35-R39 R61-R64 R68 R75 R77 R168 R169 = Resistor
R34 R41 R43 R52-R54 R57-R59 = Resistor: RES SMD 0.0OHM JUMPER 1/10W
R66 = Resistor: RES SMD 100 OHM 1% 1/10W
R93 R94 = Resistor: RES SMD 4.7K OHM 1% 1/10W
S1 S3-S5 = SW-2
S2 = SW-PB: Switch Key
U2 = TPS79633DCQ: Single Output High PSRR LDO, 1 A, Fixed 3.3 V Output, 2.7 to 5.5 V Input, 6-pin SOT-223 (DCQ), -40 to 125 degC, Green (RoHS & no Sb/Br); Manufacturer: Texas Instruments; Accuracy(%): 2; Fixed Output Options(V): 3.3; Iout(Max)(A): 1; Iq(Typ)(mA): 0.26; SubFamily: Single Channel LDO; Vdo(Typ)(mV): 220; Vin(Max)(V): 5.5; Vin(Min)(V): 2.7
U3 = TPS79613DRBR: Single Output High PSRR LDO, 1 A, Fixed 1.3 V Output, 2.7 to 5.5 V Input, 8-pin SON (DRB), -40 to 85 degC, Green (RoHS & no Sb/Br); Manufacturer: Texas Instruments; Accuracy(%): 2; Fixed Output Options(V): 1.3; Iout(Max)(A): 1; Iq(Typ)(mA): 0.26; SubFamily: Single Channel LDO; Vdo(Typ)(mV): 250; Vin(Max)(V): 5.5; Vin(Min)(V): 2.7
U4 = ADR280ARTZ-R2: Ultralow Power High PSRR Voltage Reference, 1.2 V Output, 2.4 to 5.5 V Supply, Industrial, 3-pin SOT23 (RT-3), Reel; Manufacturer: Analog Devices; Max V Supply (V): 5.5; Min V Supply (V): 2.4; Ref Out TC (ppm/C): 10; Vout: 1.2V
U5 = LT1461: 3.3V High Precision Voltage Reference
U18 = LM5017: LM5017 100-V, 600-mA Constant On-Time Synchronous Buck Regulator
VR1 VR2 = VR: VR_3386_Knob
Y1 = OSC32MHz: CRYSTAL 32.0000MHZ 20PF T/H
